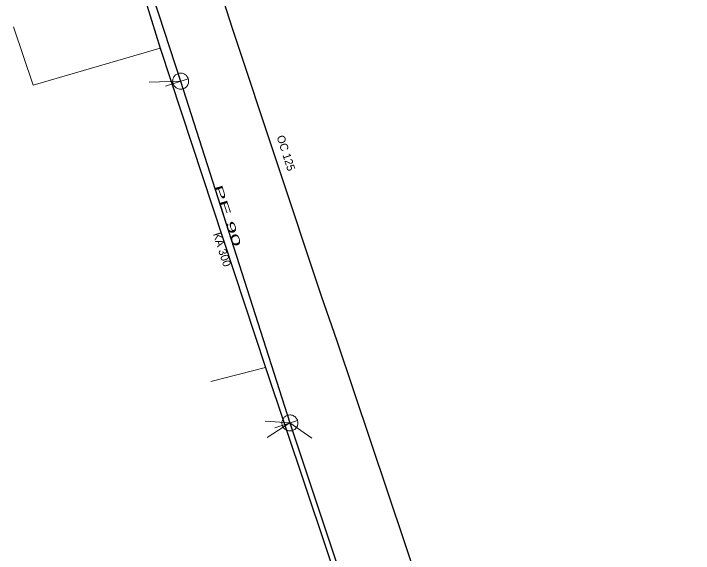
# Model space of a CAD drawing. Extents: x -807203 to -805207, y -993656 to -992505.
# Drawn here: x -807111.3 to -807026.3, y -993225.3 to -993157.9 of the extents above; entities that cross this region are included whole.
import ezdxf

# ---------------------------------------------------------------- set-up
doc = ezdxf.new("R2010")
doc.units = 0
doc.header["$LTSCALE"] = 0.4
for name, color, linetype, lineweight in [('1', 7, 'Continuous', 13), ('11', 7, 'Continuous', 13), ('13', 7, 'Continuous', 13), ('14', 7, 'Continuous', 25), ('17', 7, 'Continuous', 25), ('22', 7, 'Continuous', 13)]:
    doc.layers.add(name, color=color, linetype=linetype, lineweight=lineweight)

msp = doc.modelspace()

# ---------------------------------------------------------------- linework, layer by layer
at = {"layer": '11'}
for p, q in [((-807094.324, -993166.431), (-807090.379, -993166.289)), ((-807079.82, -993208.741), (-807076.719, -993208.969)), ((-807079.563, -993210.8), (-807076.719, -993208.969)), ((-807073.985, -993210.886), (-807076.719, -993208.969))]:
    msp.add_line(p, q, dxfattribs=at)
at = {"layer": '13'}
msp.add_line((-807079.791, -993202.06), (-807086.624, -993203.785), dxfattribs=at)
msp.add_lwpolyline([(-807092.921, -993162.154), (-807108.809, -993166.799), (-807111.259, -993159.482)], dxfattribs=at)
at = {"layer": '14'}
for p, q in [((-807098.539, -993141.399), (-807090.379, -993166.289)), ((-807090.379, -993166.289), (-807076.719, -993208.969))]:
    msp.add_line(p, q, dxfattribs=at)
msp.add_lwpolyline([(-807076.719, -993208.969), (-807068.265, -993234.297), (-807062.73, -993250.879)], dxfattribs=at)
at = {"layer": '17'}
for points in [[(-807102.744, -993101.5), (-807102.241, -993103.247), (-807100.675, -993108.116), (-807100.243, -993109.059), (-807099.234, -993112.603), (-807098.39, -993115.482), (-807094.98, -993125.833), (-807093.653, -993129.923), (-807088.842, -993144.708), (-807087.517, -993148.8), (-807087.074, -993150.114), (-807085.368, -993155.225), (-807083.942, -993159.686), (-807072.827, -993193.081), (-807070.855, -993198.727), (-807058.136, -993236.557), (-807055.798, -993243.556), (-807050.671, -993258.89), (-807046.204, -993272.388), (-807040.605, -993289.576), (-807026.284, -993334.262)], [(-807106.216, -993120.722), (-807103.627, -993128.16), (-807102.219, -993132), (-807096.589, -993150.385), (-807096.195, -993151.629), (-807092.921, -993162.153), (-807079.791, -993202.059), (-807064.89, -993246.39), (-807059.596, -993262.052), (-807055.035, -993275.397), (-807053.806, -993278.989)]]:
    msp.add_lwpolyline(points, dxfattribs=at)
at = {"layer": '22'}
for p, q in [((-807092.279, -993166.912), (-807089.429, -993165.977)), ((-807078.624, -993209.578), (-807075.767, -993208.664))]:
    msp.add_line(p, q, dxfattribs=at)
for points in [[(-807090.067, -993167.239), (-807089.966, -993167.199), (-807089.869, -993167.148), (-807089.777, -993167.087), (-807089.694, -993167.017), (-807089.618, -993166.938), (-807089.552, -993166.851), (-807089.495, -993166.757), (-807089.45, -993166.658), (-807089.415, -993166.553), (-807089.392, -993166.447), (-807089.38, -993166.338), (-807089.381, -993166.228), (-807089.394, -993166.119), (-807089.418, -993166.013), (-807089.454, -993165.909), (-807089.501, -993165.81), (-807089.558, -993165.717), (-807089.626, -993165.63), (-807089.703, -993165.552), (-807089.786, -993165.483), (-807089.879, -993165.423), (-807089.976, -993165.374), (-807090.079, -993165.335), (-807090.185, -993165.307), (-807090.293, -993165.292), (-807090.402, -993165.289), (-807090.512, -993165.298), (-807090.619, -993165.318), (-807090.724, -993165.351), (-807090.825, -993165.394), (-807090.92, -993165.447), (-807091.008, -993165.512), (-807091.09, -993165.585), (-807091.163, -993165.667), (-807091.226, -993165.757), (-807091.279, -993165.852), (-807091.321, -993165.954), (-807091.352, -993166.058), (-807091.372, -993166.166), (-807091.379, -993166.275), (-807091.375, -993166.385), (-807091.358, -993166.493), (-807091.33, -993166.599), (-807091.29, -993166.701), (-807091.239, -993166.798), (-807091.179, -993166.889), (-807091.108, -993166.973), (-807091.028, -993167.049), (-807090.942, -993167.115), (-807090.848, -993167.172), (-807090.749, -993167.218), (-807090.645, -993167.252), (-807090.538, -993167.276), (-807090.429, -993167.287), (-807090.32, -993167.287), (-807090.211, -993167.274), (-807090.104, -993167.25)], [(-807076.414, -993209.921), (-807076.312, -993209.882), (-807076.215, -993209.832), (-807076.123, -993209.771), (-807076.039, -993209.702), (-807075.962, -993209.623), (-807075.896, -993209.537), (-807075.839, -993209.443), (-807075.792, -993209.344), (-807075.756, -993209.24), (-807075.733, -993209.134), (-807075.72, -993209.025), (-807075.721, -993208.915), (-807075.733, -993208.806), (-807075.756, -993208.699), (-807075.792, -993208.595), (-807075.838, -993208.497), (-807075.894, -993208.402), (-807075.961, -993208.316), (-807076.038, -993208.237), (-807076.121, -993208.167), (-807076.213, -993208.106), (-807076.31, -993208.056), (-807076.413, -993208.017), (-807076.518, -993207.989), (-807076.626, -993207.973), (-807076.735, -993207.969), (-807076.845, -993207.977), (-807076.952, -993207.997), (-807077.058, -993208.028), (-807077.159, -993208.071), (-807077.254, -993208.124), (-807077.343, -993208.188), (-807077.425, -993208.26), (-807077.498, -993208.341), (-807077.562, -993208.431), (-807077.616, -993208.526), (-807077.659, -993208.627), (-807077.691, -993208.732), (-807077.711, -993208.839), (-807077.719, -993208.948), (-807077.715, -993209.058), (-807077.7, -993209.166), (-807077.672, -993209.273), (-807077.633, -993209.375), (-807077.583, -993209.472), (-807077.523, -993209.563), (-807077.453, -993209.648), (-807077.374, -993209.724), (-807077.287, -993209.791), (-807077.194, -993209.848), (-807077.095, -993209.895), (-807076.992, -993209.931), (-807076.885, -993209.955), (-807076.776, -993209.967), (-807076.667, -993209.967), (-807076.558, -993209.955), (-807076.451, -993209.932)]]:
    msp.add_lwpolyline(points, close=True, dxfattribs=at)

# ---------------------------------------------------------------- texts
at = {"layer": '1'}
for s, p in [('OC 125', (-807078.396, -993173.225)), ('KA 300', (-807086.354, -993185.377))]:
    msp.add_text(s, height=1, rotation=288, dxfattribs=at).set_placement(p)
at = {"layer": '1', "width": 2.2}
msp.add_text('PE 90 ', height=1, rotation=288, dxfattribs=at).set_placement((-807086.201, -993179.423))

doc.saveas('drawing.dxf')
